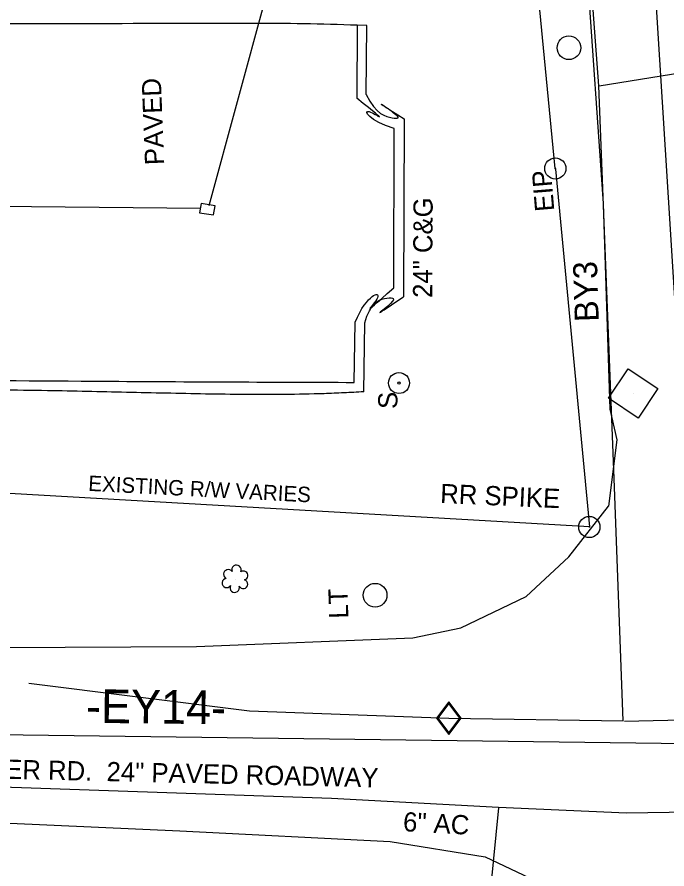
# Model space of a CAD drawing. Extents: x 1627482 to 1629573, y 760826 to 766301.
# Drawn here: x 1628197 to 1628332.3, y 764811 to 764988.4 of the extents above; entities that cross this region are included whole.
import ezdxf

# ---------------------------------------------------------------- set-up
doc = ezdxf.new("R2010")
doc.units = 0
for name, color, linetype in [('CTL Secondary Horizontal and Vertical CELL', 7, 'Continuous'), ('CTL Secondary Horizontal and Vertical Text', 7, 'Continuous'), ('Exist Horizontal Alignment', 7, 'Continuous'), ('Exist Horizontal Alignment Direction Label', 7, 'Continuous'), ('Exist Other Culture Sign Post CELL', 7, 'Continuous'), ('Exist Other Culture Sign Post Text', 7, 'Continuous'), ('Exist Property Iron Pin CELL', 7, 'Continuous'), ('Exist Property Iron Pin Text', 7, 'Continuous'), ('Exist Right of Way Line', 7, 'Continuous'), ('Exist Right of Way Line Text', 7, 'Continuous'), ('Exist Roads Curbs', 7, 'Continuous'), ('Exist Roads Curbs Text', 7, 'Continuous'), ('Exist Roads EOP', 7, 'Continuous'), ('Exist Roads EOP Other', 7, 'Continuous'), ('Exist Roads EOP Text', 7, 'Continuous'), ('Exist Roads EOT', 7, 'Continuous'), ('Exist Structure Minor Drop Inlet', 7, 'Continuous'), ('Exist Structure Minor Pipes HDPE 15 Inch', 7, 'Continuous'), ('Exist Utilities Gas UG Line SUE LOS B', 7, 'Continuous'), ('Exist Utilities Gas Valve CELL', 7, 'Continuous'), ('Exist Utilities Other Pole CELL', 7, 'Continuous'), ('Exist Utilities Other Pole Text', 7, 'Continuous'), ('Exist Utilities Water UG Line SUE LOS B', 7, 'Continuous'), ('Exist Utilities Water UG Line SUE LOS B Text', 7, 'Continuous'), ('Exist Vegetation Shrub CELL', 7, 'Continuous')]:
    doc.layers.add(name, color=color, linetype=linetype)

# ---------------------------------------------------------------- blocks, each defined once
blk = doc.blocks.new('EXIST PROPERTY IRON PIN_368')
at = {"layer": 'Exist Property Iron Pin CELL'}
for radius in [3.356748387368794, 0.10776307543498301]:
    blk.add_circle((-2.079104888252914e-10, 3.0320279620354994e-11), radius, dxfattribs=at)
blk = doc.blocks.new('CTL SECONDARY HORIZONTAL AND VERTICAL')
at = {"layer": 'CTL Secondary Horizontal and Vertical CELL'}
blk.add_line((0, 0), (0, 0), dxfattribs=at)
blk.add_lwpolyline([(-0.10429825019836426, 0.0003535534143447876), (0.0005303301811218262, 0.10518213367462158), (0.10553568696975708, 0.00017677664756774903), (0.0007071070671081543, -0.10465180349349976)], close=True, dxfattribs=at)

msp = doc.modelspace()

# ---------------------------------------------------------------- linework, layer by layer
at = {"layer": 'Exist Horizontal Alignment'}
msp.add_line((1628151.9601007, 764839.55444704), (1628347.9286044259, 764837.0098619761), dxfattribs=at)
msp.add_arc((1620544.2759937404, 764447.7339661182), 7813.355859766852, 2.258189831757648, 5.9470481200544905, dxfattribs=at)
at = {"layer": 'Exist Other Culture Sign Post CELL'}
for radius in [2.1799154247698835, 0.24011715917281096]:
    msp.add_circle((1628276.523, 764912.1889999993), radius, dxfattribs=at)
at = {"layer": 'Exist Right of Way Line'}
for points in [[(1628301.7391688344, 765031.574446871), (1628308.9393769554, 764956.8710340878)], [(1628309.0738050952, 764956.6838149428), (1628316.1367612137, 764882.217332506)], [(1628316.1367612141, 764882.2173325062), (1628136.2421493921, 764892.6224989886)]]:
    msp.add_lwpolyline(points, dxfattribs=at)
at = {"layer": 'Exist Roads Curbs'}
for p, q in [((1628269.818, 764986.6519999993), (1628267.787, 764986.6680000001)), ((1628269.71, 764972.2629999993), (1628269.818, 764986.6519999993)), ((1628277.628, 764967.1839999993), (1628277.4340000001, 764930.1429999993)), ((1628269.175, 764910.3709999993), (1628269.382, 764924.6949999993))]:
    msp.add_line(p, q, dxfattribs=at)
for points in [[(1628269.71, 764972.2629999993), (1628271.798, 764968.0419999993), (1628275.751, 764967.2119999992), (1628277.628, 764967.1839999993), (1628269.71, 764972.2629999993), (1628277.628, 764967.1839999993)], [(1628269.382, 764924.6949999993), (1628270.635, 764928.8579999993), (1628273.578, 764930.0499999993), (1628277.4340000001, 764930.1429999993), (1628269.382, 764924.6949999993), (1628277.4340000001, 764930.1429999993)]]:
    msp.add_open_spline(points, degree=3, dxfattribs=at)
msp.add_spline([(1628269.175, 764910.371), (1628265.0624914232, 764910.1381060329), (1628260.9478245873, 764909.9719178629), (1628252.7204506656, 764909.7939625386), (1628236.265318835, 764909.9030827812), (1628219.8102442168, 764910.250166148), (1628203.355, 764910.593), (1628193.4221753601, 764910.7213471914), (1628183.488812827, 764910.801801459), (1628163.622, 764910.848)], degree=3, dxfattribs=at)
at = {"layer": 'Exist Roads EOP'}
for points in [[(1628315.596242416, 764998.3420401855), (1628319.001, 764949.5489000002), (1628320.414, 764906.7764), (1628321.834, 764900.3289), (1628320.150910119, 764886.5805522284)], [(1628150.643, 764856.9707), (1628193.332, 764857.133), (1628234.415, 764857.3713), (1628279.409, 764859.144), (1628289.419, 764861.2023), (1628302.9987823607, 764867.7237944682), (1628311.854, 764876.0147), (1628320.150910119, 764886.5805522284)], [(1628142.235, 764822.5291), (1628186.2280000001, 764820.9717000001), (1628230.891, 764818.9683), (1628274.652, 764816.7169), (1628294.4581179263, 764813.5617935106), (1628307.6638003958, 764807.3062263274), (1628315.974, 764801.5203), (1628323.4286103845, 764792.9474789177), (1628330.18, 764781.1492), (1628330.009, 764780.2597), (1628331.176, 764769.0084000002), (1628332.004, 764752.6177)]]:
    msp.add_lwpolyline(points, dxfattribs=at)
at = {"layer": 'Exist Roads EOP Other'}
for p, q in [((1628267.787, 764986.6679999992), (1628267.746, 764971.4669999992)), ((1628275.4270000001, 764932.0129999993), (1628275.549, 764965.2129999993)), ((1628267.2210000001, 764912.3229999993), (1628267.374, 764924.8609999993))]:
    msp.add_line(p, q, dxfattribs=at)
for points in [[(1628267.787, 764986.6680000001), (1628256.7183733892, 764986.9814808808), (1628245.6494205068, 764987.0589539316), (1628223.511, 764987.018), (1628150.134, 764987.297), (1628143.4713701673, 764987.426266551), (1628140.140129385, 764987.4655002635), (1628138.4745478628, 764987.4486450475), (1628137.6417693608, 764987.4273341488), (1628136.8090000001, 764987.3960000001)], [(1628165.9408687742, 764912.7661292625), (1628169.68, 764912.7760000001), (1628213.124, 764912.577), (1628267.2210000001, 764912.323)]]:
    msp.add_spline(points, degree=3, dxfattribs=at)
for points in [[(1628275.549, 764965.2129999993), (1628270.219, 764966.7019999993), (1628267.746, 764971.4669999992), (1628275.549, 764965.2129999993), (1628267.746, 764971.4669999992)], [(1628267.374, 764924.8609999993), (1628269.963, 764930.8269999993), (1628275.4270000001, 764932.0129999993), (1628267.374, 764924.8609999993), (1628275.4270000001, 764932.0129999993)]]:
    msp.add_open_spline(points, degree=3, dxfattribs=at)
at = {"layer": 'Exist Roads EOT'}
msp.add_lwpolyline([(1628321.8900000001, 765097.9763), (1628325.7750000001, 765049.0365), (1628329.467, 764999.3778000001), (1628332.5150000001, 764950.8177), (1628335.69, 764901.0454), (1628336.888, 764880.4277000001)], dxfattribs=at)
at = {"layer": 'Exist Structure Minor Drop Inlet'}
msp.add_lwpolyline([(1628235.026, 764947.6529999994), (1628237.9230491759, 764947.1709970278), (1628238.239, 764949.0699999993), (1628235.3419508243, 764949.5520029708)], close=True, dxfattribs=at)
at = {"layer": 'Exist Structure Minor Pipes HDPE 15 Inch'}
for p, q in [((1628237.0087494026, 764949.1787032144), (1628256.369, 765020.2939999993)), ((1628128.0586537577, 764949.607678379), (1628235.286423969, 764948.5760348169))]:
    msp.add_line(p, q, dxfattribs=at)
at = {"layer": 'Exist Utilities Gas UG Line SUE LOS B'}
for points in [[(1628199.4623, 764849.7382), (1628245.3853, 764843.9277000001), (1628286.9133, 764842.4425), (1628323.2083, 764841.8858), (1628321.4064000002, 764890.5206), (1628318.081, 764974.0716), (1628312.7903, 765045.731), (1628307.6495, 765115.9388), (1628300.965, 765190.2503), (1628294.7206, 765274.1337), (1628289.3031, 765336.6749), (1628283.5302, 765391.0982), (1628278.3977, 765447.267), (1628276.2077, 765471.8347)], [(1628422.0566, 764971.8189), (1628396.1231, 764979.7377), (1628358.9189, 764978.3382000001), (1628335.3544, 764976.7876), (1628318.1988, 764974.0191)], [(1628413.9855, 763549.8288000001), (1628410.6069, 763659.7593), (1628406.7208, 763757.7262), (1628401.3031, 763877.1827000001), (1628398.45, 763915.2697), (1628395.9346000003, 763992.3905), (1628393.095, 764066.2966), (1628389.9231, 764168.1623), (1628388.2974, 764264.4148000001), (1628388.8649, 764316.2432), (1628388.6642, 764366.2876), (1628385.6053, 764456.2035000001), (1628379.3174, 764518.1987), (1628376.0105, 764570.0466), (1628373.6887, 764583.536), (1628373.6561, 764583.5242), (1628369.0436, 764671.9168), (1628368.8092, 764733.4728), (1628365.4713000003, 764801.3026), (1628365.4103000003, 764842.6691), (1628323.4549000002, 764841.7289)]]:
    msp.add_lwpolyline(points, dxfattribs=at)
at = {"layer": 'Exist Utilities Gas Valve CELL'}
msp.add_line((1628286.8932, 764842.4166), (1628286.8932, 764842.4166), dxfattribs=at)
msp.add_lwpolyline([(1628286.8932, 764845.8291000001), (1628284.3557000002, 764842.4166), (1628286.8932, 764839.0041), (1628289.4307000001, 764842.4166), (1628286.8932, 764845.8291000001)], dxfattribs=at)
msp.add_lwpolyline([(1628289.1814671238, 764842.4166), (1628286.8932, 764845.493924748), (1628284.6049328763, 764842.4166), (1628286.8932, 764839.339275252)], close=True, dxfattribs=at)
at = {"layer": 'Exist Utilities Other Pole CELL'}
for centre in [(1628311.8882638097, 764981.9871789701), (1628271.5556132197, 764868.0130801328)]:
    msp.add_circle(centre, 2.463293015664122, dxfattribs=at)
at = {"layer": 'Exist Utilities Water UG Line SUE LOS B'}
msp.add_line((1628297.1999, 764823.7735), (1628295.4713000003, 764805.5899), dxfattribs=at)
msp.add_lwpolyline([(1628183.7538, 764828.4623000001), (1628262.4598, 764825.7695), (1628297.2594, 764823.8989), (1628323.8997000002, 764822.7286), (1628355.0329000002, 764823.1733000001), (1628361.45, 764823.2226000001)], dxfattribs=at)
at = {"layer": 'Exist Vegetation Shrub CELL'}
msp.add_line((1628242.47012043, 764871.2479123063), (1628242.47012043, 764871.2479123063), dxfattribs=at)
for centre, radius, start, end in [((1628240.987374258, 764872.3747031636), 0.9678345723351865, 35.89076388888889, 245.42164722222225), ((1628242.6989706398, 764873.2883518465), 0.9900450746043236, 334.8390694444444, 200.47173888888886), ((1628244.1421402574, 764872.1168299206), 0.9287983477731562, 284.45671944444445, 126.08612222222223), ((1628240.669859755, 764870.5435219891), 0.9548337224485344, 95.10992222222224, 327.95341111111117), ((1628244.107176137, 764870.3189101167), 0.9373148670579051, 204.99133055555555, 73.46011666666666), ((1628242.3417699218, 764869.564233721), 0.9835814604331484, 151.2796583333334, 21.387019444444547)]:
    msp.add_arc(centre, radius, start, end, dxfattribs=at)

# ---------------------------------------------------------------- block references
at = {"layer": 'CTL Secondary Horizontal and Vertical CELL', "xscale": 50.000000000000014, "yscale": 50.00000000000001, "rotation": 11.16983302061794}
msp.add_blockref('CTL SECONDARY HORIZONTAL AND VERTICAL', (1628325.2364, 764910.0019999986), dxfattribs=at)
at = {"layer": 'Exist Property Iron Pin CELL', "xscale": 0.6561666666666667, "yscale": 0.6561666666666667}
for p in [(1628309.0574753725, 764956.8559832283), (1628316.1367612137, 764882.217332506)]:
    msp.add_blockref('EXIST PROPERTY IRON PIN_368', p, dxfattribs=at)

# ---------------------------------------------------------------- texts
at = {"layer": 'CTL Secondary Horizontal and Vertical Text'}
msp.add_text('BY3', height=5, rotation=91.77133955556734, dxfattribs=at).set_placement((1628318.1067897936, 764924.9933306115))
at = {"layer": 'Exist Horizontal Alignment Direction Label'}
msp.add_text('-EY14-', height=6.9999999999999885, rotation=359.37539869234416, dxfattribs=at).set_placement((1628211.3625371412, 764841.4532013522))
at = {"layer": 'Exist Other Culture Sign Post Text'}
msp.add_text('S', height=4, rotation=90, dxfattribs=at).set_placement((1628276.2005017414, 764906.7898710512))
at = {"layer": 'Exist Property Iron Pin Text'}
for s, rotation, p in [('EIP', 94.74953010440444, (1628308.859686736, 764948.0597138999)), ('RR SPIKE', 357.4901148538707, (1628285.034839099, 764887.2217964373))]:
    msp.add_text(s, height=3.9999919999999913, rotation=rotation, dxfattribs=at).set_placement(p)
at = {"layer": 'Exist Right of Way Line Text'}
msp.add_text('EXISTING R/W VARIES', height=3.1999999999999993, rotation=357.0109303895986, dxfattribs=at).set_placement((1628211.798182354, 764889.7492339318))
at = {"layer": 'Exist Roads Curbs Text'}
msp.add_text('24" C&G', height=4, rotation=89.69991955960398, dxfattribs=at).set_placement((1628283.4328247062, 764929.9028853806))
at = {"layer": 'Exist Roads EOP Text'}
for s, height, rotation, p in [('PAVED', 4, 92.25818983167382, (1628227.6722964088, 764957.6463754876)), ('BIESECKER RD.  24" PAVED ROADWAY', 4.000000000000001, 358.6688172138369, (1628171.3552819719, 764830.345011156))]:
    msp.add_text(s, height=height, rotation=rotation, dxfattribs=at).set_placement(p)
at = {"layer": 'Exist Utilities Other Pole Text'}
msp.add_text('LT', height=4, rotation=91.77133955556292, dxfattribs=at).set_placement((1628265.9992992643, 764863.2048858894))
at = {"layer": 'Exist Utilities Water UG Line SUE LOS B Text'}
msp.add_text('6" AC', height=3.9999999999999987, rotation=356.9231130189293, dxfattribs=at).set_placement((1628277.286512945, 764818.8939496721))

doc.saveas('drawing.dxf')
